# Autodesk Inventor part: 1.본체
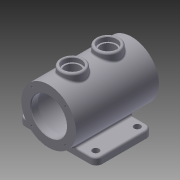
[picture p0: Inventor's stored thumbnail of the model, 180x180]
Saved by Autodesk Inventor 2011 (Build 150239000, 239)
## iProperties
Created: 2015-04
Part Number: 1.본체
Document SubType Name: Modeling
Designer: user
Density: 2.71 g/cm^3
Material: 알루미늄-6061
Mass: 1283.67 g
Surface Area: 1047 cm^2
Volume: 473.679 cm^3
Author: user
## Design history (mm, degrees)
sketch "스케치1"
  geometry: L1 (-65, 47.5)-(65, 47.5); L2 (65, 47.5)-(65, -47.5); L3 (65, -47.5)-(-65, -47.5); L4 (-65, -47.5)-(-65, 47.5); 3 further points
  constraints: 8 end point, 2 midpoint, 2 parallel, 1 horizontal, 1 horizontal alignment, 1 perpendicular, 1 vertical alignment
  dimensions: "d0" = 130 distance of L2.end L3.end; "d1" = 95 distance of L1.end L2.end
extrude "돌출1" new body sketch "스케치1" distance "d2" = 12; taper "d3" = 0 deg
sketch "스케치2"
  geometry: L1 (47.5, 12)-(47.5, 0) reference; L2 (47.5, 0)-(-47.5, 0) reference; L3 (-47.5, 0)-(-47.5, 12) reference; L4 (-47.5, 12)-(47.5, 12) reference; L5 (77.5, 50)-(-62.5, 50); L6 (77.5, 96)-(-62.5, 96); L7 (77.5, 96)-(77.5, 80); L8 (77.5, 80)-(65.5, 80); L9 (65.5, 80)-(65.5, 87.5); L10 (65.5, 87.5)-(-50.5, 87.5); L11 (-50.5, 87.5)-(-50.5, 80); L12 (-50.5, 80)-(-62.5, 80); L13 (-62.5, 80)-(-62.5, 96); 1 further point
  constraints: 18 end point, 5 parallel, 2 perpendicular, 2 vertical alignment, 1 collinear, 1 horizontal alignment
  dimensions: "d4" = 50 vertical distance of L2.end L5.end; "d5" = 140 distance of L5.start L5.end; "d6" = 15 horizontal distance of L3.end L5.end; "d7" = 12 distance of L7.end L8.end; "d8" = 12 distance of L11.end L12.end; "d9" = 60 diameter of L12 L5; "d10" = 75 diameter of L10 L5; "d12" = 92 diameter of L6 L5
revolve "회전1" sketch "스케치2" stored, may be unused: angle "d13" = 90 deg
node "작업 평면1"
sketch "스케치3"
  geometry: L1 (0, -70)-(0, 70) reference; C1 r 20 at (0, 30); C2 r 20 at (0, -30); 3 further points
  constraints: 3 point on line, 2 centre point, 2 coincident
  dimensions: "d14" = 40 distance of point (0, 30) L1.end; "d15" = 40 distance of L1.start point (0, -30); "d16" = 40 diameter of C1; "d17" = 40 diameter of C2
extrude "돌출2" join sketch "스케치3" distance "d18" = 10; taper "d19" = 0 deg
sketch "스케치4"
  geometry: L1 (0, -50)-(0, -10) reference; A1 r 20 centre (0, -30) between (0, -10) and (0, -50) reference; 1 further point
extrude "돌출3" join sketch "스케치4" stored distance "d20" = 10; taper "d21" = 0 deg
sketch "스케치5"
  geometry: L1 (0, -50)-(0, -10) reference; A1 r 20 centre (0, -30) between (0, -50) and (0, -10) reference; 1 further point
extrude "돌출4" join sketch "스케치5" stored distance "d22" = 10; taper "d23" = 0 deg
sketch "스케치6"
  geometry: L1 (0, 10)-(0, 50) reference; A1 r 20 centre (0, 30) between (0, 10) and (0, 50) reference; 1 further point
extrude "돌출5" join sketch "스케치6" stored distance "d24" = 10; taper "d25" = 0 deg
sketch "스케치7"
  geometry: L1 (0, 10)-(0, 50) reference; A1 r 20 centre (0, 30) between (0, 50) and (0, 10) reference; 1 further point
extrude "돌출6" join sketch "스케치7" stored distance "d26" = 8; taper "d27" = 0 deg
sketch "스케치8"
  geometry: C1 r 20 at (0, 0) reference; C2 r 15 at (0, 0); 1 further point
  constraints: 1 centre point, 1 coincident
  dimensions: "d28" = 30 diameter of C2
extrude "돌출7" cut sketch "스케치8" distance "d29" = 8; taper "d30" = 0 deg
sketch "스케치9"
  geometry: C1 r 15 at (0, 0) reference; C2 r 12.5 at (0, 0); 1 further point
  constraints: 1 centre point, 1 coincident
  dimensions: "d31" = 25 diameter of C2
extrude "돌출8" cut sketch "스케치9" stored distance "d32" = 8; taper "d33" = 0 deg
sketch "스케치10"
  geometry: C1 r 20 at (0, 0) reference; C2 r 15 at (0, 0); 1 further point
  constraints: 1 centre point, 1 coincident
  dimensions: "d34" = 30 diameter of C2
extrude "돌출9" cut sketch "스케치10" distance "d35" = 8; taper "d36" = 0 deg
sketch "스케치11"
  geometry: C1 r 15 at (0, 0) reference; C2 r 12.5 at (0, 0); 1 further point
  constraints: 1 centre point, 1 coincident
  dimensions: "d37" = 25 diameter of C2
extrude "돌출10" cut sketch "스케치11" stored distance "d38" = 8; taper "d39" = 0 deg
sketch "스케치12" dims "d40" = 80
  geometry: L1 (0, 0)-(28.284, 28.284); L2 (0, 0)-(40, 0); C1 r 30 at (0, 0) reference; 2 further points
  constraints: 4 end point, 2 coincident, 1 equal length, 1 horizontal, 3 other
  dimensions: "d41" = 45 deg angle of L2 L1
hole "Hole1" sketch "스케치12" at (28.284, 28.284) diameter "d42" = 3.242; stored, may be unused: countersink angle "d46" = 90 deg, drill point angle "d48" = 118 deg; dims "d43" = 8, "d44" = 4, "d45" = 2, "d47" = 10
node "작업 평면2"
fillet "모깎기2" dims "d53" = 10
fillet "모깎기3" dims "d54" = 10
fillet "모깎기4" dims "d61" = 3
fillet "모깎기5" dims "d62" = 3
fillet "모깎기6" dims "d63" = 3
fillet "모깎기7" dims "d64" = 3
fillet "모깎기8" dims "d65" = 3
chamfer "모따기2" distance "d69" = 1; stored, may be unused: second distance "d70" = 2, angle "d71" = 45 deg
sketch "스케치16"
  geometry: L1 (55, 47.5)-(-55, 47.5) reference; L2 (52, 35)-(-52, 35); C1 r 5.5 at (52, 35); C2 r 5.5 at (-52, 35); 3 further points
  constraints: 2 centre point, 2 end point, 2 midpoint, 1 parallel, 1 vertical alignment
  dimensions: "d75" = 11 diameter of C1; "d76" = 11 diameter of C2; "d77" = 104 distance of L2.end L2.start; "d78" = 12.5 distance between parallel lines of L1 L2
extrude "돌출13" cut sketch "스케치16" stored distance "d79" = 8; taper "d80" = 0 deg
sketch "스케치17"
  geometry: L1 (-62, -37.5)-(-62, 37.5) reference; L2 (-45.989, 21.757)-(-45.989, -21.757); L3 (-45.989, -21.757)-(-62.011, -21.757); L4 (-62.011, -21.757)-(-62.011, 21.757); L5 (-62.011, 21.757)-(-45.989, 21.757); L6 (-45.989, 21.757)-(-62.011, 21.757); L7 (-62.011, 21.757)-(-62.011, -21.757); L8 (-62.011, -21.757)-(-45.989, -21.757); L9 (-45.989, -21.757)-(-45.989, 21.757); L10 (-45.989, 21.757)-(-62.011, -21.757); L11 (-45.989, -21.757)-(-62.011, 21.757); C1 r 5.5 at (-52, 35) reference; 2 further points
  constraints: 12 end point, 2 parallel, 1 horizontal, 1 midpoint, 1 perpendicular, 2 other
  dimensions: "d81" = 35 vertical distance of C1.centre point (-54, 0); "d82" = 8 distance from line of L1 point (-54, 0)
feature "엠보싱1" sketch "스케치17" dims "d0" = 130, "d1" = 95, "d83" = 1, "d84" = 0
sketch "스케치18"
  geometry: 1 further point
chamfer "모따기3" distance "d85" = 1; stored, may be unused: second distance "d86" = 2, angle "d87" = 45 deg
node "솔리드1"
pattern_circular "원형 패턴1" dims angle "d50" = 360 deg
mirror "대칭1"
mirror "대칭3"
node "작업 평면4"
node "절단 모서리 투영1"
node "절단 모서리 투영2"
